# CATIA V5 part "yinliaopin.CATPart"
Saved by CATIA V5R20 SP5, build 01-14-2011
Part number: Part1
Material "Wallpaper Strip 2": density 2120 kg/m3, Young's modulus 2.56e+10 Pa, Poisson ratio 0.22
Material "Alcantara": density 900 kg/m3
Material "Alcantara": density 900 kg/m3
Bounding box of the stored display mesh (mm): x -25 to 25, y -26 to 25, z 0 to 110
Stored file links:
  D:\请勿打开\嗯嗯\别打开了\嗯哼\不听？\180122236\新建文件夹\yinliaopin.CATPart
  C:\Program Files\Dassault Systemes\B20\intel_a\startup\materials\Catalog.CATMaterial
  C:\Program Files\Dassault Systemes\B20\intel_a\startup\materials\blue_env_512x512.jpg
  C:\Program Files\Dassault Systemes\B20\intel_a\startup\materials\chessboard.jpg
  C:\Program Files\Dassault Systemes\B20\intel_a\startup\materials\alcantara.jpg
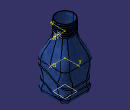
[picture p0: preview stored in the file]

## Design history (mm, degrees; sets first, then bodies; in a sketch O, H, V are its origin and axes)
Set1, material "Alcantara"
  Sketch1 on face of Pad1 from Sketch3.L1, origin (25, 0, 0), H (0, 1, 0), V (0, 0, 1)
    spline S1 through (-40, 10) (-10, 20) (10, 10) (30, 20)
  Extrude1: Element1 Sketch1, Lim1 66, Lim2 66
  MultiSel1: CommonCtxFeats ({extract ExtractElem face of Fillet1}; {extract ExtractElem face of Pad1 from Sketch3.L1}; {extract ExtractElem face of Fillet1}; {extract ExtractElem face of Pad1 from Sketch3.L4}; {extract ExtractElem face of Fillet1}; {extract ExtractElem face of Pad1 from Sketch3.L3}; {extract ExtractElem face of Fillet1}; {extract ExtractElem face of Pad1 from Sketch3.L2})
  Sketch2 on face of Pad1 from Sketch3.L3, origin (-25, 0, 0), H (0, -1, 0), V (0, 0, 1)
    spline S1 through (-40, 20) (-10, 30) (10, 40) (30, 40)
  Extrude2: Element1 Sketch2, Lim1 66, Lim2 66
  MultiSel2: CommonCtxFeats ({extract ExtractElem face of Fillet1}; {extract ExtractElem face of Pad1 from Sketch3.L2}; {extract ExtractElem face of Fillet1}; {extract ExtractElem face of Pad1 from Sketch3.L1}; {extract ExtractElem face of Fillet1}; {extract ExtractElem face of Pad1 from Sketch3.L4}; {extract ExtractElem face of Fillet1}; {extract ExtractElem face of Pad1 from Sketch3.L3})
  Join1: Elements ({intersect ToIntersect1 {extract ExtractElem face of Fillet1}, ToIntersect2 Extrude2}; {intersect ToIntersect1 {extract ExtractElem face of Pad1 from Sketch3.L2}, ToIntersect2 Extrude2}; {intersect ToIntersect1 {extract ExtractElem face of Fillet1}, ToIntersect2 Extrude2}; {intersect ToIntersect1 {extract ExtractElem face of Pad1 from Sketch3.L1}, ToIntersect2 Extrude2}; {intersect ToIntersect1 {extract ExtractElem face of Fillet1}, ToIntersect2 Extrude2}; {intersect ToIntersect1 {extract ExtractElem face of Pad1 from Sketch3.L4}, ToIntersect2 Extrude2}; {intersect ToIntersect1 {extract ExtractElem face of Fillet1}, ToIntersect2 Extrude2}; {intersect ToIntersect1 {extract ExtractElem face of Pad1 from Sketch3.L3}, ToIntersect2 Extrude2})
  Join2: Elements ({intersect ToIntersect1 {extract ExtractElem face of Fillet1}, ToIntersect2 Extrude1}; {intersect ToIntersect1 {extract ExtractElem face of Pad1 from Sketch3.L1}, ToIntersect2 Extrude1}; {intersect ToIntersect1 {extract ExtractElem face of Fillet1}, ToIntersect2 Extrude1}; {intersect ToIntersect1 {extract ExtractElem face of Pad1 from Sketch3.L4}, ToIntersect2 Extrude1}; {intersect ToIntersect1 {extract ExtractElem face of Fillet1}, ToIntersect2 Extrude1}; {intersect ToIntersect1 {extract ExtractElem face of Pad1 from Sketch3.L3}, ToIntersect2 Extrude1}; {intersect ToIntersect1 {extract ExtractElem face of Fillet1}, ToIntersect2 Extrude1}; {intersect ToIntersect1 {extract ExtractElem face of Pad1 from Sketch3.L2}, ToIntersect2 Extrude1})
  Plane1: type Normal, Curve Join1, RefPoint vertex [face of MultiSel2 | face of MultiSel2]
  Circle1: type CtrRad, Start 0, End 180, Center vertex [face of MultiSel2 | face of MultiSel2], Support Plane1, Radius 1, FirstDirection (1, 0, 0)
  Plane2: type Normal, Curve Join2, RefPoint vertex [face of MultiSel1 | face of MultiSel1]
  Circle2: type CtrRad, Start 0, End 180, Center vertex [face of MultiSel1 | face of MultiSel1], Support Plane2, Radius 1, FirstDirection (1, 0, 0)
Body1 (main body), material "Alcantara"
  Set2
    Sketch3 on xy-plane, origin (0, 0, 0), H (1, 0, 0), V (0, 1, 0)
      line L1 (25, 25) -> (25, -25)
      line L2 (25, -25) -> (-25, -25)
      line L3 (-25, -25) -> (-25, 25)
      line L4 (-25, 25) -> (25, 25)
      distance L2 L4 = 50
      distance L1 L3 = 50
      vertical: L1 V, L3 V
      horizontal: L2 H, L4 H
      equidistance: L1 L3 O, L2 L4 O
  Pad1: profile Sketch3, direction (0, 0, 1), length 50
  Fillet1: on edge [face of Pad1 from Sketch3.L2 | face of Pad1 from Sketch3.L3]; edge [face of Pad1 from Sketch3.L4 | face of Pad1 from Sketch3.L1]; edge [face of Pad1 from Sketch3.L3 | face of Pad1 from Sketch3.L4]; edge [face of Pad1 from Sketch3.L1 | face of Pad1 from Sketch3.L2]
  Fillet2: on edge [start face of Pad1 | face of Pad1 from Sketch3.L4]
  Plane3: type Offset, RefPlane end face of Pad1, Offset 40, reversed
  Sketch4 on Plane3, origin (0, 0, 90), H (1, 0, 0), V (0, -1, 0)
    circle A1 centre (0, 0) radius 15
    radius A1 = 15
  Pad2: profile Sketch4, direction (0, 0, -1), length -20
  Sketch5 on end face of Pad1, origin (0, 0, 50), H (1, 0, 0), V (0, 1, 0)
    point P1 (25, 0)
    distance V P1 = 25
    coincidence: P1 H
  Sketch6 on start face of Pad2, origin (0, 0, 90), H (1, 0, 0), V (0, -1, 0)
    point P1 (15, 0)
    distance P1 V = 15
    coincidence: P1 H
  Loft1: solid, Sections ({boundary Boundary {extract ExtractElem end face of Pad1}}; {boundary Boundary {extract ExtractElem start face of Pad2}}), StartFace end face of Pad1, EndFace start face of Pad2
  Slot1: profile Circle1, centre curve Join1
  Slot2: profile Circle2, centre curve Join2
  Shell1: ExtOffset 0, Face end face of Pad2, IntOffset 1
  Point1: (0, 0, 2), relative to Sketch6
  Helix1: Direction Z axis, RefPoint Point1, Pitch 3, Height 16, TaperAngle 0
  Point2: type OnCurve, Support Helix1, Length 5
  Line1: type PtDir, RefPoint Point1, Direction (1, 0, 0), Start 0, End -10
  Point3: type OnCurve, Support Line1, Length 5
  Connect1: Curve1 Line1, Point1 vertex of Line1, Tension1 1, Curve2 Helix1, Point2 Point2, Tension2 1
  Plane4: type Normal, Curve Connect1, RefPoint vertex of Connect1
  Circle3: type CtrRad, Start 0, End 180, Center vertex of Connect1, Support Plane4, Radius 0.5, FirstDirection (0, 1, 0)
  Rib1: profile Circle3, centre curve Connect1
  Body2
    Plane5: type Offset, RefPlane xy-plane, Offset 2
    Sketch7 on Plane5, origin (0, 0, 2), H (1, 0, 0), V (0, 1, 0)
      circle A1 centre (0, 0) radius 14
    Pad3: profile Sketch7, direction (0, 0, 1), length 120
  Remove1: tool Body2
Body3
Body4, material "Wallpaper Strip 2"
  Sketch8 on face of Pad1 from Sketch3.L2, origin (0, -25, 0), H (1, 0, 0), V (0, 0, 1)
    polyline C1
    polyline C2
    polyline C3
    polyline C4
    polyline C5
    polyline C6
    polyline C7
    polyline C8
    polyline C9
    polyline C10
    polyline C11
  Pad4: profile Sketch8, direction (0, -1, 0), length 1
